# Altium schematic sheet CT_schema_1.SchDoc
size 607 x 588 mm
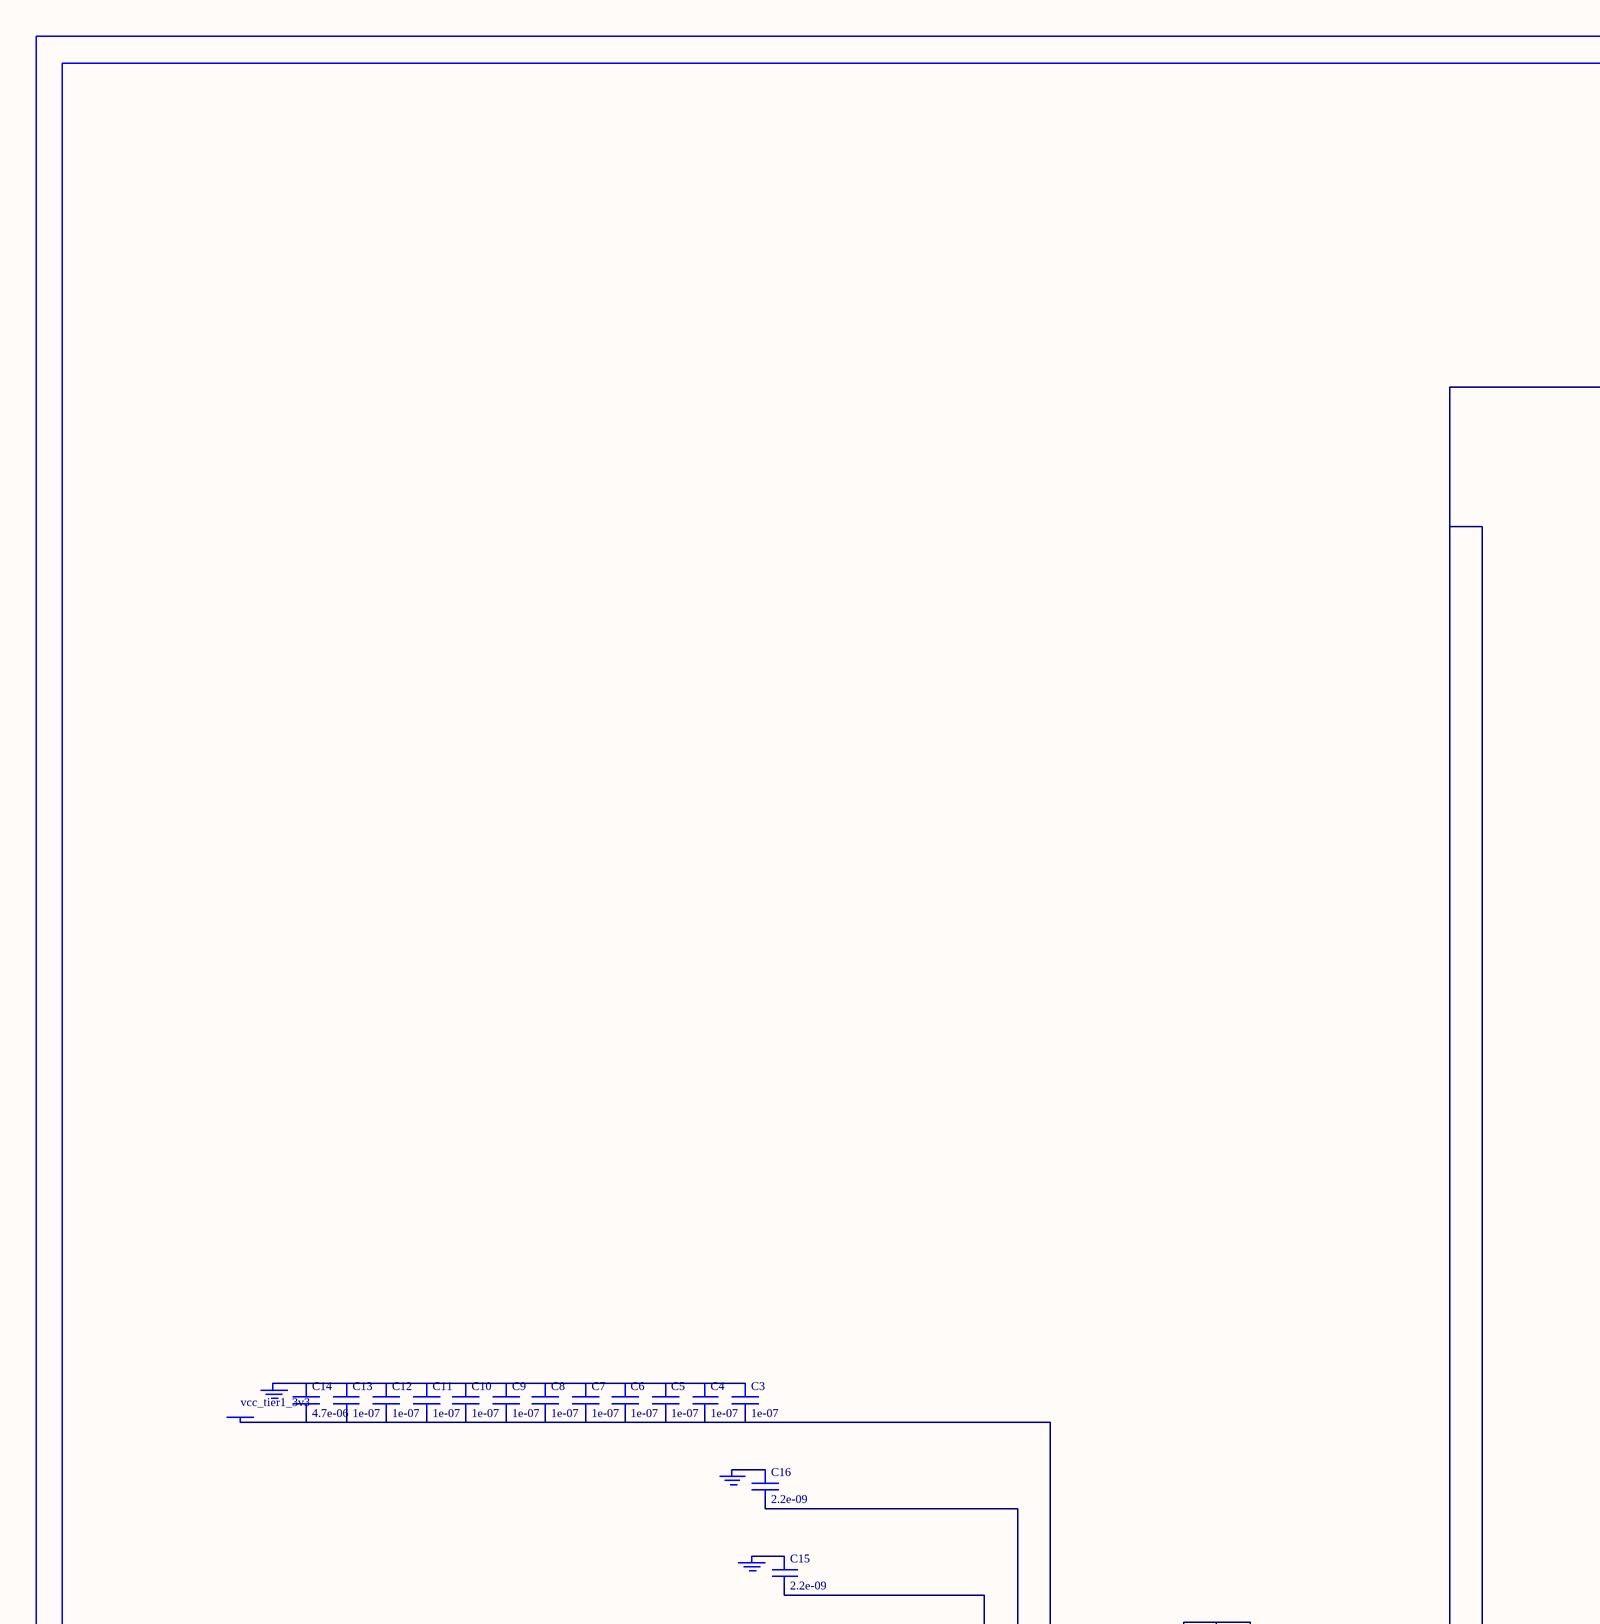
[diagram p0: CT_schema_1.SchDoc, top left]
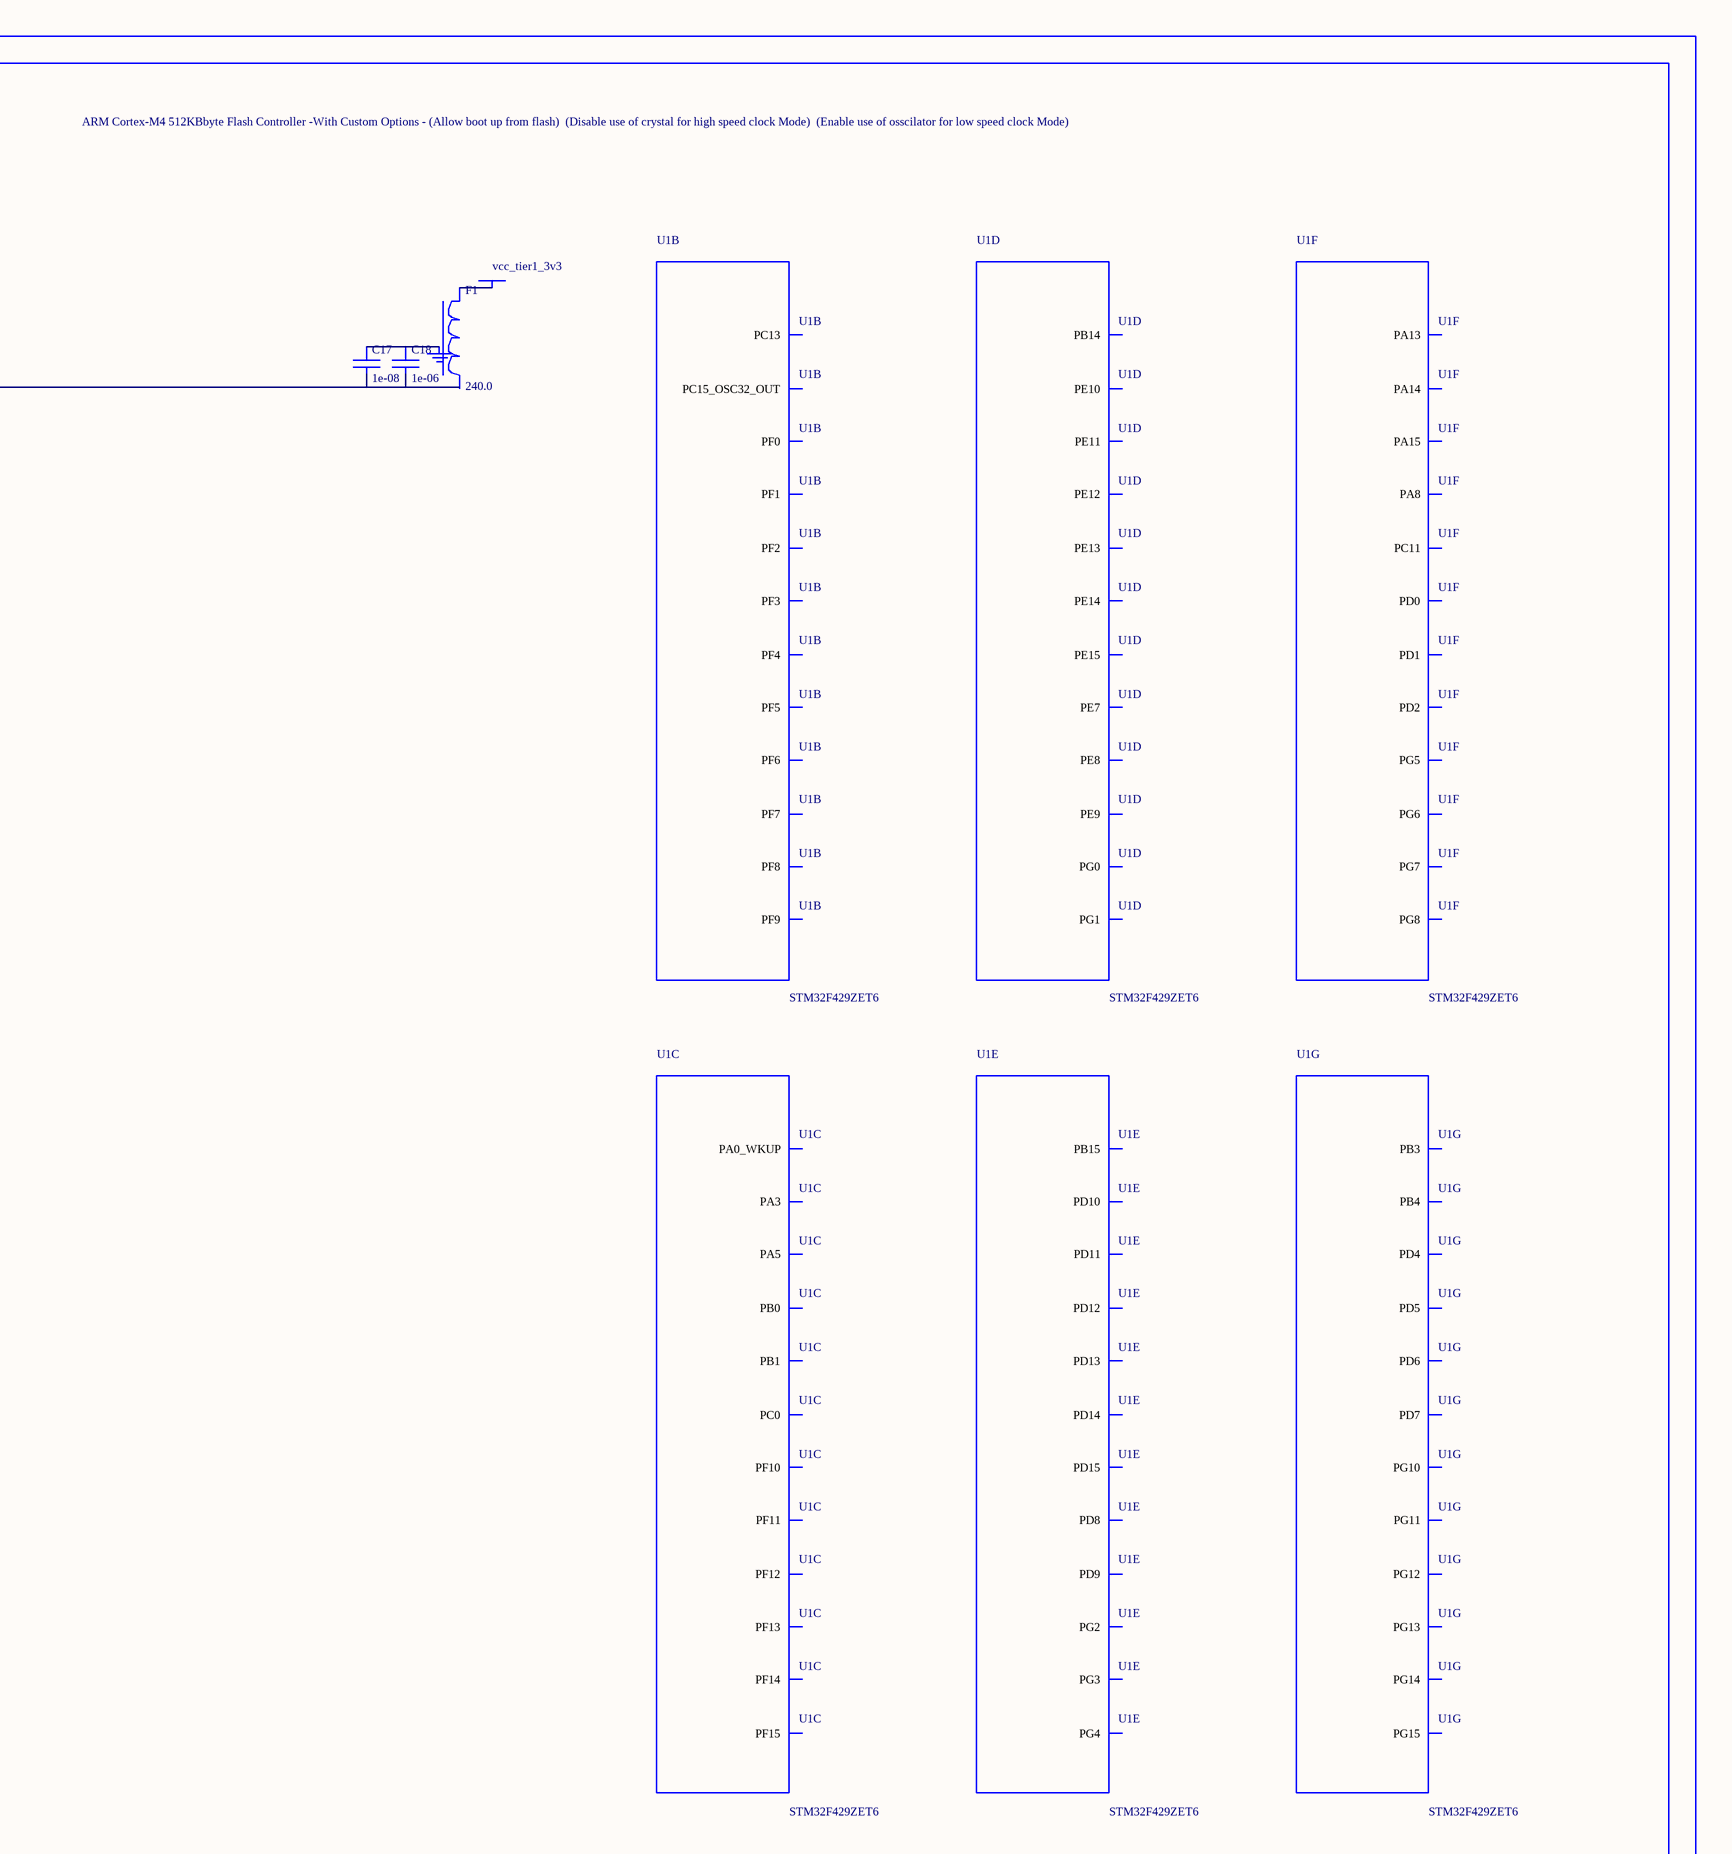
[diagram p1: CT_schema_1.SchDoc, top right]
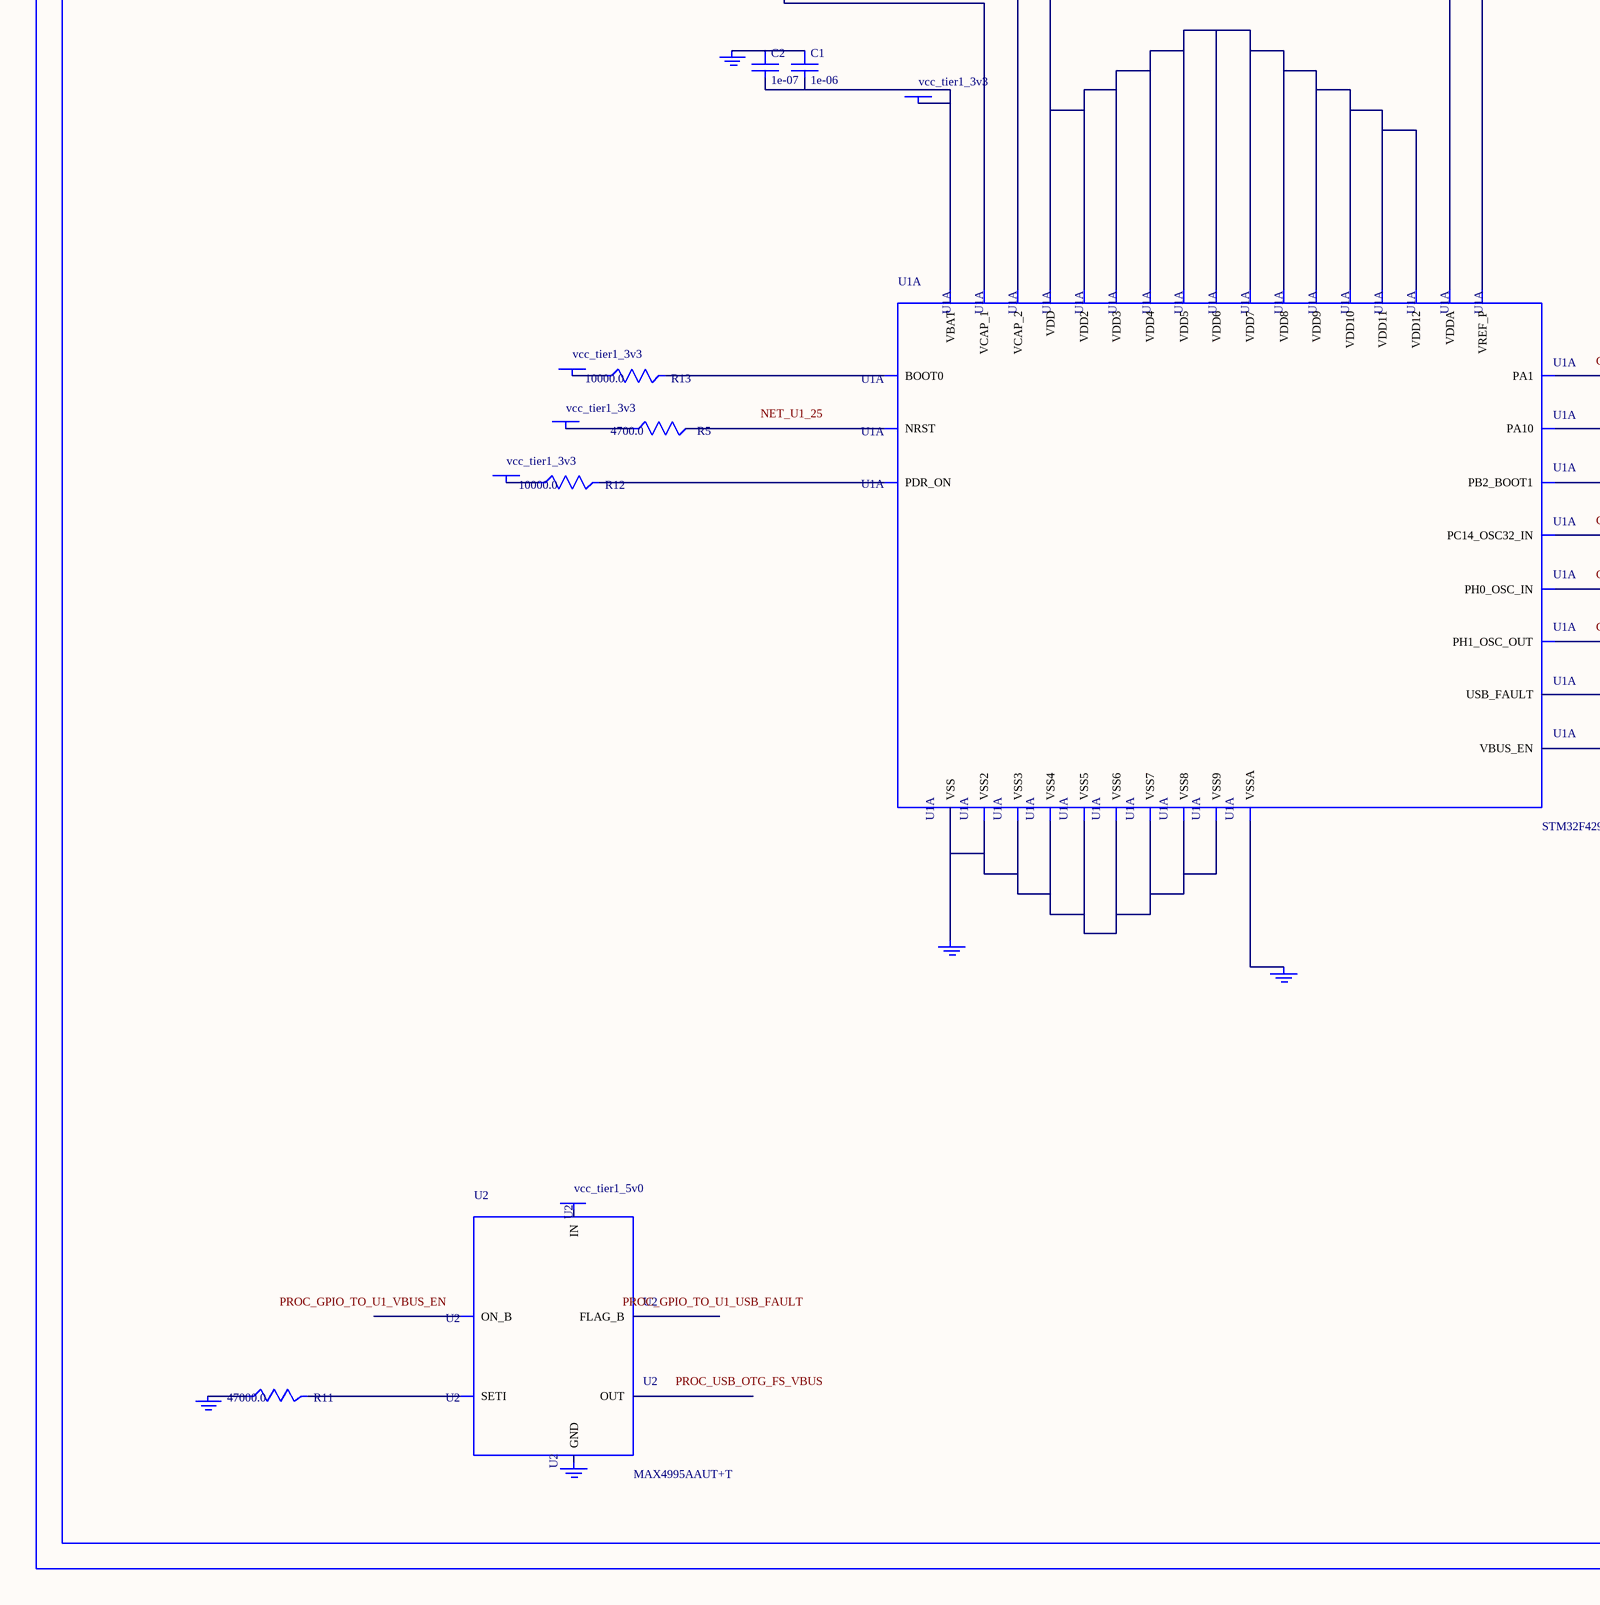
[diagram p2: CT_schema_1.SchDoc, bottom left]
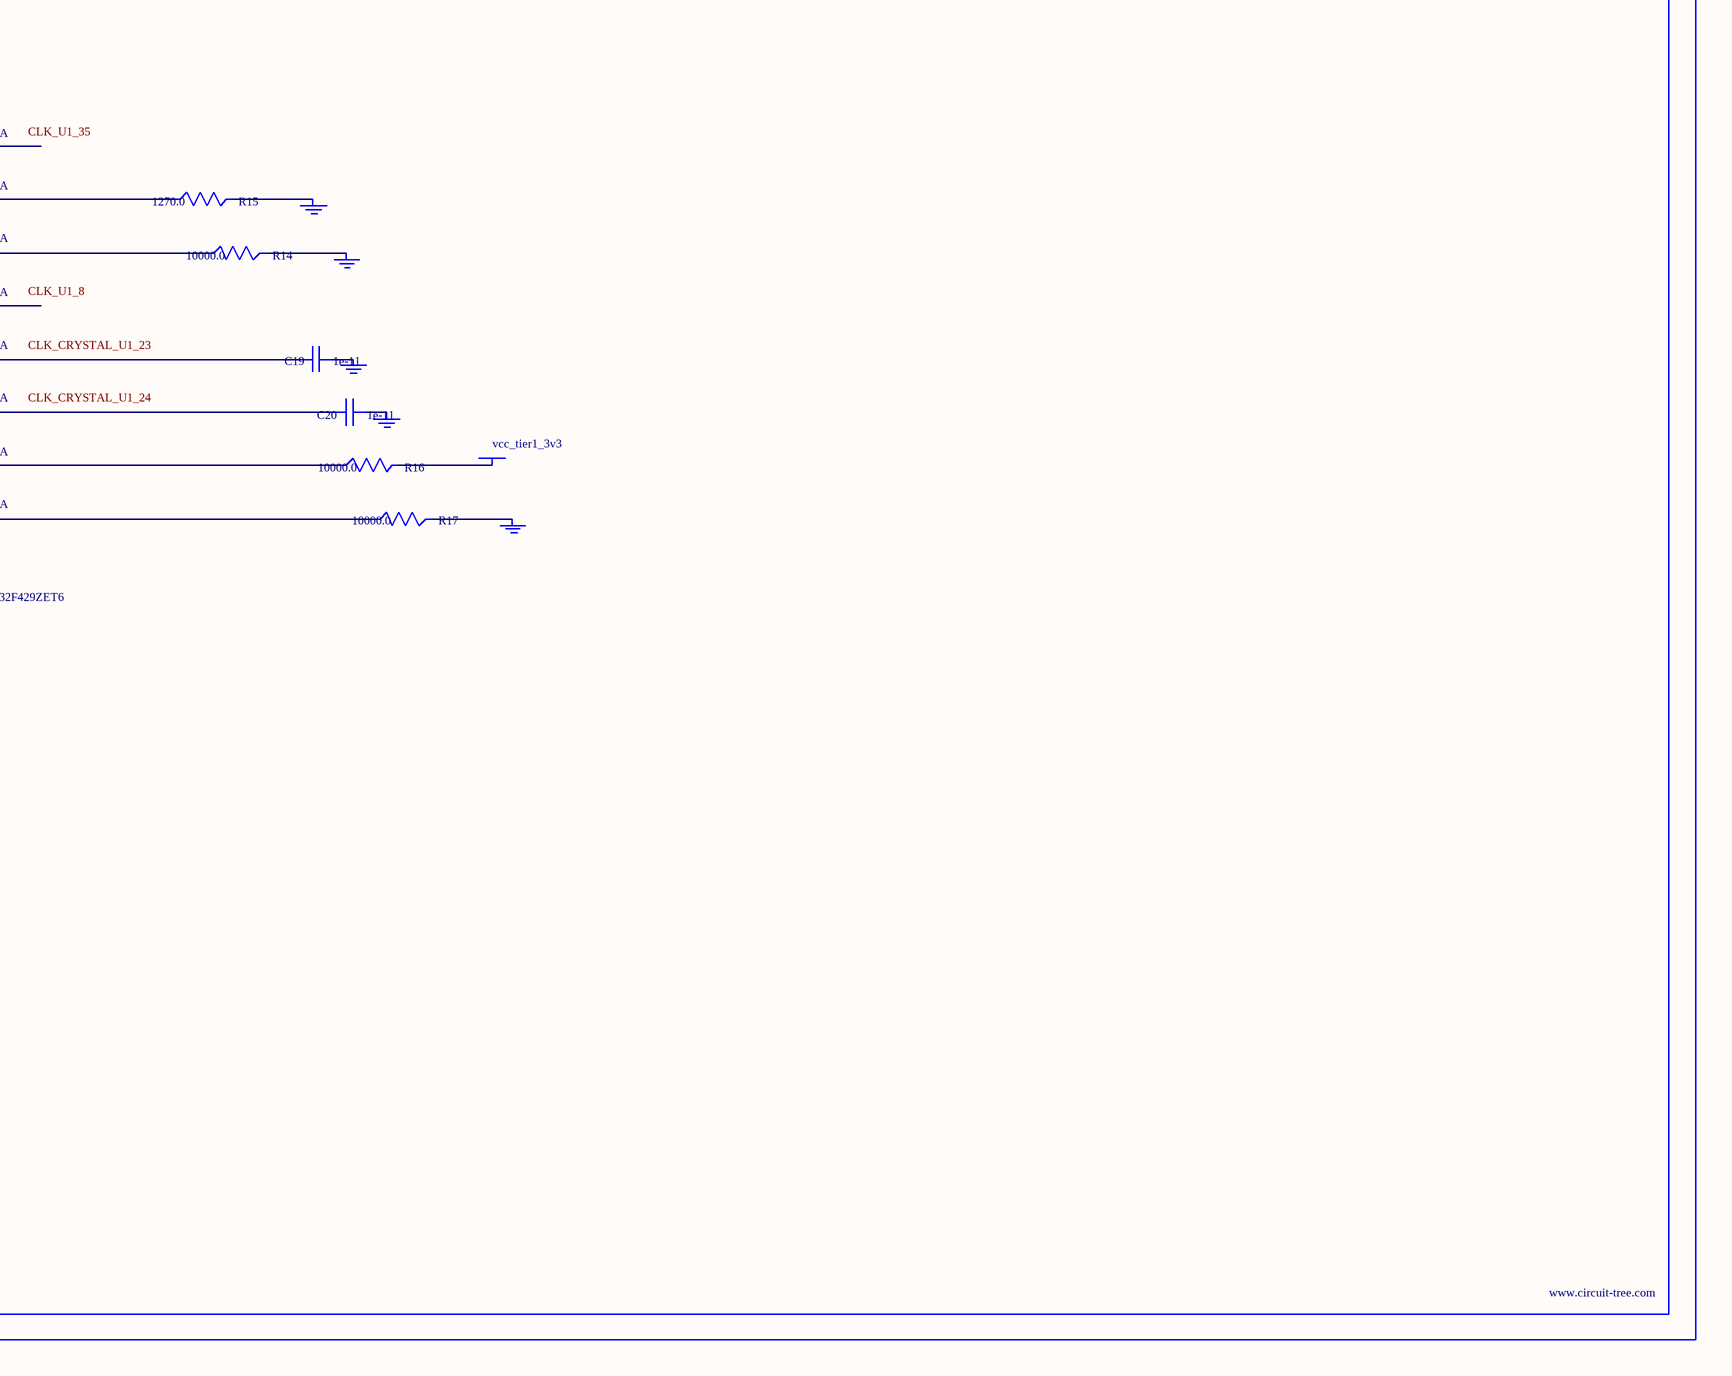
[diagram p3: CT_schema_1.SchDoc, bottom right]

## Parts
BORDER0  (no value)
C1  1e-06  [C0603]
C2  1e-07  [C0603]
C3  1e-07  [C0603]
C4  1e-07  [C0603]
C5  1e-07  [C0603]
C6  1e-07  [C0603]
C7  1e-07  [C0603]
C8  1e-07  [C0603]
C9  1e-07  [C0603]
C10  1e-07  [C0603]
C11  1e-07  [C0603]
C12  1e-07  [C0603]
C13  1e-07  [C0603]
C14  4.7e-06  [C0603]
C15  2.2e-09  [C0603]
C16  2.2e-09  [C0603]
C17  1e-08  [C0603]
C18  1e-06  [C0603]
C19  1e-11  [C0402]
C20  1e-11  [C0402]
F1  240.0  [L0603]
GND_INSTANCE_0_0  (no value)
GND_INSTANCE_0_1  (no value)
GND_INSTANCE_0_2  (no value)
GND_INSTANCE_0_3  (no value)
GND_INSTANCE_0_4  (no value)
GND_INSTANCE_0_5  (no value)
GND_INSTANCE_0_6  (no value)
GND_INSTANCE_0_7  (no value)
GND_INSTANCE_0_8  (no value)
GND_INSTANCE_0_9  (no value)
GND_INSTANCE_0_10  (no value)
GND_INSTANCE_0_11  (no value)
GND_INSTANCE_0_12  (no value)
GND_INSTANCE_0_13  (no value)
POWER_INSTANCE_0_0  vcc_tier1_3v3
POWER_INSTANCE_0_1  vcc_tier1_3v3
POWER_INSTANCE_0_2  vcc_tier1_3v3
POWER_INSTANCE_0_3  vcc_tier1_3v3
POWER_INSTANCE_0_4  vcc_tier1_3v3
POWER_INSTANCE_0_5  vcc_tier1_3v3
POWER_INSTANCE_0_6  vcc_tier1_3v3
POWER_INSTANCE_0_7  vcc_tier1_5v0
R5  4700.0  [R0603]
R11  47000.0  [R0603]
R12  10000.0  [R0603]
R13  10000.0  [R0603]
R14  10000.0  [R0603]
R15  1270.0  [R0603]
R16  10000.0  [R0603]
R17  10000.0  [R0603]
U1  STM32F429ZET6  [LQFP144]  (parts A,B,C,D,E,F,G of 11)
U2  MAX4995AAUT+T  [SOT-23-6]

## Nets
NetC1_1: C1.1 C2.1 GND_INSTANCE_0_1.0(GND)
NetC1_2: C1.2 C2.2 POWER_INSTANCE_0_1.0(PWR) U1.6(VBAT)
NetC3_1: C3.1 C4.1 C5.1 C6.1 C7.1 C8.1 C9.1 C10.1 C11.1 C12.1 C13.1 C14.1 GND_INSTANCE_0_2.0(GND)
NetC3_2: C3.2 C4.2 C5.2 C6.2 C7.2 C8.2 C9.2 C10.2 C11.2 C12.2 C13.2 C14.2 POWER_INSTANCE_0_2.0(PWR) U1.17(VDD) U1.30(VDD2) U1.39(VDD3) U1.52(VDD4) U1.62(VDD5) U1.72(VDD6) U1.84(VDD7) U1.95(VDD8) U1.108(VDD9) U1.121(VDD10) U1.131(VDD11) U1.144(VDD12)
NetC15_1: C15.1 GND_INSTANCE_0_8.0(GND)
NetC15_2: C15.2 U1.71(VCAP_1)
NetC16_1: C16.1 GND_INSTANCE_0_10.0(GND)
NetC16_2: C16.2 U1.106(VCAP_2)
NetC17_1: C17.1 C18.1 GND_INSTANCE_0_6.0(GND)
NetC17_2: C17.2 C18.2 U1.32(VREF_P) U1.33(VDDA)
NetC19_1: C19.1 GND_INSTANCE_0_3.0(GND)
NetC19_2: C19.2 U1.23(PH0_OSC_IN)
NetC20_1: C20.1 GND_INSTANCE_0_4.0(GND)
NetC20_2: C20.2 U1.24(PH1_OSC_OUT)
NetF1_1: F1.1 POWER_INSTANCE_0_3.0(PWR)
NetGND_INSTANCE_0_0_0: GND_INSTANCE_0_0.0(GND) R17.2
NetGND_INSTANCE_0_5_0: GND_INSTANCE_0_5.0(GND) U1.31(VSSA)
NetGND_INSTANCE_0_7_0: GND_INSTANCE_0_7.0(GND) R14.2
NetGND_INSTANCE_0_9_0: GND_INSTANCE_0_9.0(GND) R15.2
NetGND_INSTANCE_0_11_0: GND_INSTANCE_0_11.0(GND) U1.16(VSS) U1.38(VSS2) U1.51(VSS3) U1.61(VSS4) U1.83(VSS5) U1.94(VSS6) U1.107(VSS7) U1.120(VSS8) U1.130(VSS9)
NetGND_INSTANCE_0_12_0: GND_INSTANCE_0_12.0(GND) R11.1
NetPOWER_INSTANCE_0_0_0: POWER_INSTANCE_0_0.0(PWR) R16.2
NetPOWER_INSTANCE_0_4_0: POWER_INSTANCE_0_4.0(PWR) R13.1
NetPOWER_INSTANCE_0_5_0: POWER_INSTANCE_0_5.0(PWR) R12.1
NetPOWER_INSTANCE_0_6_0: POWER_INSTANCE_0_6.0(PWR) R5.1
NetR5_2: R5.2 U1.25(NRST)
NetR11_2: R11.2 U2.3(SETI)
NetR12_2: R12.2 U1.143(PDR_ON)
NetR13_2: R13.2 U1.138(BOOT0)
NetR14_1: R14.1 U1.48(PB2_BOOT1)
NetR15_1: R15.1 U1.102(PA10)
NetR16_1: R16.1 U1.2(USB_FAULT)
NetR17_1: R17.1 U1.1(VBUS_EN)

Not connected (* = marked no-connect by the designer): F1 2; GND_INSTANCE_0_13 0(GND); POWER_INSTANCE_0_7 0(PWR); U1 7(PC13) 8(PC14_OSC32_IN) 9(PC15_OSC32_OUT) 10(PF0) 11(PF1) 12(PF2) 13(PF3) 14(PF4) 15(PF5) 18(PF6) 19(PF7) 20(PF8) 21(PF9) 22(PF10) 26(PC0) 34(PA0_WKUP) 35(PA1) 37(PA3) 41(PA5) 46(PB0) 47(PB1) 49(PF11) 50(PF12) 53(PF13) 54(PF14) 55(PF15) 56(PG0) 57(PG1) 58(PE7) 59(PE8) 60(PE9) 63(PE10) 64(PE11) 65(PE12) 66(PE13) 67(PE14) 68(PE15) 75(PB14) 76(PB15) 77(PD8) 78(PD9) 79(PD10) 80(PD11) 81(PD12) 82(PD13) 85(PD14) 86(PD15) 87(PG2) 88(PG3) 89(PG4) 90(PG5) 91(PG6) 92(PG7) 93(PG8) 100(PA8) 105(PA13) 109(PA14) 110(PA15) 112(PC11) 114(PD0) 115(PD1) 116(PD2) 118(PD4) 119(PD5) 122(PD6) 123(PD7) 125(PG10) 126(PG11) 127(PG12) 128(PG13) 129(PG14) 132(PG15) 133(PB3) 134(PB4); U2 1(OUT) 2(GND) 4(ON_B) 5(IN) 6(FLAG_B)

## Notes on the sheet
- Labels drawn without touching a wire or pin: CLK_CRYSTAL_U1_23, CLK_CRYSTAL_U1_24, CLK_U1_8, CLK_U1_35, NET_U1_25, PROC_GPIO_TO_U1_USB_FAULT, PROC_GPIO_TO_U1_VBUS_EN, PROC_USB_OTG_FS_VBUS

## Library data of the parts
BORDER0 = BORDER_PAGE0
C1 C18 = C0603C105K3RACTU
C2-C13 = 06035C104K4Z2A
C14 = GRM188R6YA475KE15D
C15 C16 = 06031C222KAZ2A
C17 = 06035C103K4Z2A
C19 C20 = C0402C100K3GACTU
F1 = Z0603C241ASMST
GND_INSTANCE_0_0-GND_INSTANCE_0_13 = GND
POWER_INSTANCE_0_0-POWER_INSTANCE_0_7 = PWR
R5 = RC0603JR-074K7L
R11 = RC0603JR-0747KL
R12-R14 R16 R17 = RC0603JR-0710KL
R15 = RC0603FR-071K27L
